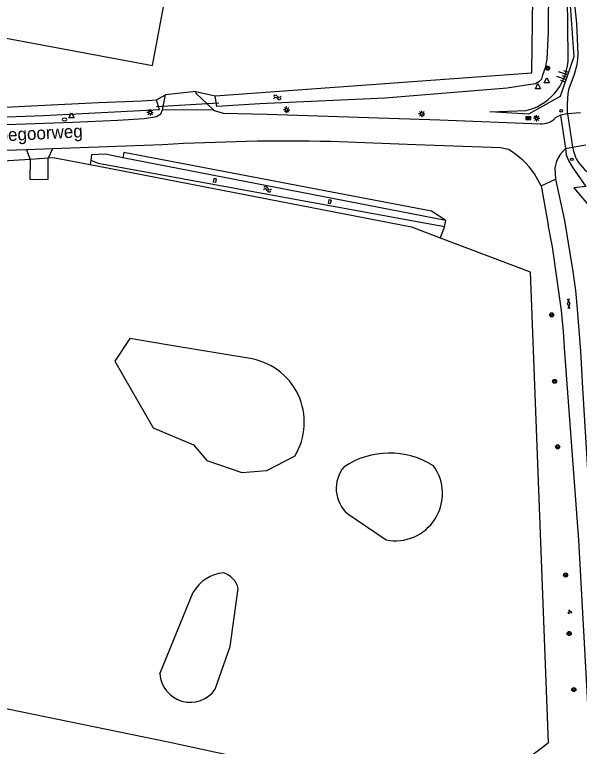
# Model space of a CAD drawing. Extents: x 132994 to 136000, y 393499 to 395512.
# Drawn here: x 133766.6 to 133877.6, y 394251.1 to 394394.8 of the extents above; entities that cross this region are included whole.
import ezdxf

# ---------------------------------------------------------------- set-up
doc = ezdxf.new("R2010")
doc.units = 0
for name, color, linetype in [('gg-afsc-draadraster', 7, 'Continuous'), ('gg-afsc-hekwerk', 7, 'Continuous'), ('gg-anno-openbare ruimte label', 7, 'Continuous'), ('gg-bbg-hoofdgebouw', 7, 'Continuous'), ('gg-knt-BGT kruinlijn', 7, 'Continuous'), ('gg-knt-bovenkant onderkant talud', 7, 'Continuous'), ('gg-knt-bronhoudergrens', 7, 'Continuous'), ('gg-knt-onverhard', 7, 'Continuous'), ('gg-knt-verharding', 7, 'Continuous'), ('gg-kntw-bovenkant insteek waterloop', 7, 'Continuous'), ('gg-kwrk-duiker nz buis', 7, 'Continuous'), ('gt-grn-groengrens', 7, 'Continuous'), ('gt-grn-weggrens', 7, 'Continuous'), ('gt-symb-boom', 7, 'Continuous'), ('gt-symb-brandkraan', 7, 'Continuous'), ('gt-symb-elektrakast', 7, 'Continuous'), ('gt-symb-gesloten verharding', 7, 'Continuous'), ('gt-symb-groenvak', 7, 'Continuous'), ('gt-symb-kolk center center', 7, 'Continuous'), ('gt-symb-lichtmast', 7, 'Continuous'), ('gt-symb-talud symbool', 7, 'Continuous'), ('gt-symb-verkeersbordpaal', 7, 'Continuous'), ('gt-symb-waterafsluiter', 7, 'Continuous'), ('gt-symb-watersymbool', 7, 'Continuous')]:
    doc.layers.add(name, color=color, linetype=linetype)

# ---------------------------------------------------------------- blocks, each defined once
blk = doc.blocks.new('gt0-WAFSL')
at = {"layer": 'gt-symb-waterafsluiter'}
for p, q in [((-0.5, -0.33), (0, 0.67)), ((0, 0.67), (0.5, -0.33)), ((0.5, -0.33), (-0.5, -0.33))]:
    blk.add_line(p, q, dxfattribs=at)
blk = doc.blocks.new('gt0-BOOM')
at = {"layer": 'gt-symb-boom'}
for radius in [0.4, 0.2]:
    blk.add_circle((0, 0), radius, dxfattribs=at)
blk = doc.blocks.new('gt0-TALUD_1')
at = {"layer": 'gt-symb-talud symbool'}
for p, q in [((-1, -1), (-1, 0)), ((-0.5, -2), (-0.5, 0)), ((0, -1), (0, 0)), ((0.5, -2), (0.5, 0)), ((1, -1), (1, 0))]:
    blk.add_line(p, q, dxfattribs=at)
blk = doc.blocks.new('gt0-LMAST')
at = {"layer": 'gt-symb-lichtmast'}
for p, q in [((-0.18, 0.17), (-0.45, 0.44)), ((0, 0.25), (0, 0.62)), ((0.17, 0.17), (0.44, 0.44)), ((-0.25, 0), (-0.63, 0)), ((-0.18, -0.18), (-0.45, -0.45)), ((0, -0.25), (0, -0.63)), ((0.44, -0.45), (0.17, -0.18)), ((0.25, 0), (0.62, 0))]:
    blk.add_line(p, q, dxfattribs=at)
blk.add_circle((0, 0), 0.25, dxfattribs=at)
blk = doc.blocks.new('gt0-VPAAL')
at = {"layer": 'gt-symb-verkeersbordpaal'}
blk.add_circle((0, 0), 0.25, dxfattribs=at)
blk = doc.blocks.new('gt0-GRVAK')
at = {"layer": 'gt-symb-groenvak'}
for p, q in [((-0.11, 0.19), (-0.23, 0.24)), ((-0.18, 0.15), (0.09, 0.15)), ((-0.09, 0.21), (-0.16, 0.32)), ((-0.05, 0.21), (-0.05, 0.39)), ((0, 0.21), (0.06, 0.32)), ((0.01, 0.19), (0.13, 0.24)), ((0.26, -0.05), (0.2, 0.06)), ((0.3, -0.05), (0.3, 0.13)), ((0.35, -0.05), (0.41, 0.06)), ((-0.25, -0.23), (-0.36, -0.18)), ((-0.32, -0.26), (-0.05, -0.26)), ((-0.23, -0.21), (-0.29, -0.1)), ((-0.18, -0.2), (-0.18, -0.02)), ((-0.14, -0.21), (-0.07, -0.1)), ((-0.12, -0.23), (0, -0.18)), ((0.24, -0.07), (0.12, -0.02)), ((0.17, -0.11), (0.44, -0.11)), ((0.37, -0.07), (0.49, -0.02))]:
    blk.add_line(p, q, dxfattribs=at)
blk = doc.blocks.new('gt0-GESVH1')
at = {"layer": 'gt-symb-gesloten verharding'}
for p, q in [((-0.99, -0.26), (0.01, 0.24)), ((0.01, -0.26), (-0.99, 0.24)), ((0.01, 0.24), (1.01, -0.26)), ((1.01, 0.24), (0.01, -0.26))]:
    blk.add_line(p, q, dxfattribs=at)
blk = doc.blocks.new('gt0-WA')
at = {"layer": 'gt-symb-watersymbool'}
for centre, start, end in [((-0.32, 0.02), 28.0725, 151.9275), ((0.43, 0.42), 208.0725, 331.9275), ((-0.32, -0.43), 28.0725, 151.9275), ((0.43, -0.03), 208.0725, 331.9275)]:
    blk.add_arc(centre, 0.425, start, end, dxfattribs=at)
blk = doc.blocks.new('gt0-EKAST')
at = {"layer": 'gt-symb-elektrakast'}
for p, q in [((-0.5, -0.25), (0.5, 0.25)), ((-0.5, 0.25), (0.5, -0.25))]:
    blk.add_line(p, q, dxfattribs=at)
blk.add_lwpolyline([(0.5, 0.25), (-0.5, 0.25), (-0.5, -0.25), (0.5, -0.25)], close=True, dxfattribs=at)
blk = doc.blocks.new('gt0-KOLKCC')
at = {"layer": 'gt-symb-kolk center center'}
blk.add_lwpolyline([(-0.38, 0.2), (0.38, 0.2), (0.38, -0.2), (-0.38, -0.2)], close=True, dxfattribs=at)
blk = doc.blocks.new('gt0-BR')
at = {"layer": 'gt-symb-brandkraan'}
for centre, radius, start, end in [((-0.24, 0), 0.206, 107.5669, 252.4331), ((0.6, -2.66), 3, 106.892, 107.5669), ((0, -0.69), 0.938, 73.108, 106.892), ((-0.6, -2.66), 3, 72.4331, 73.108), ((0.24, 0), 0.206, 287.567, 72.4331), ((0.6, 2.66), 3, 252.4331, 253.108), ((0, 0.69), 0.938, 253.108, 286.8921), ((-0.6, 2.66), 3, 286.8921, 287.567)]:
    blk.add_arc(centre, radius, start, end, dxfattribs=at)

msp = doc.modelspace()

# ---------------------------------------------------------------- linework, layer by layer
at = {"layer": 'gg-afsc-draadraster'}
for p, q in [((133769.7, 394366.38), (133751.16, 394365.24)), ((133773.24, 394366.6), (133769.7, 394366.38)), ((133774.53, 394366.68), (133773.24, 394366.6)), ((133774.53, 394366.68), (133781.44, 394365.34)), ((133850.21, 394350.97), (133867.86, 394344.26)), ((133867.86, 394344.26), (133871.43, 394251.79)), ((133854.87, 394239.41), (133871.43, 394251.79))]:
    msp.add_line(p, q, dxfattribs=at)
for points in [[(133781.44, 394365.34), (133844.57, 394353.11), (133850.21, 394350.97)], [(133837.36, 394243.19), (133796.78, 394251.96), (133765.58, 394258.32), (133761.44, 394259.55), (133756.92, 394262.08), (133753.62, 394264.61), (133733.16, 394282.25), (133750.17, 394360.68)]]:
    msp.add_lwpolyline(points, dxfattribs=at)
at = {"layer": 'gg-afsc-hekwerk'}
for p, q in [((133868.22, 394383.61), (133868.54, 394411.09)), ((133802.23, 394379.67), (133796.25, 394379.02))]:
    msp.add_line(p, q, dxfattribs=at)
at = {"layer": 'gg-bbg-hoofdgebouw'}
msp.add_lwpolyline([(133766.81, 394480.12), (133766.45, 394478.19), (133740.48, 394483.05), (133727.52, 394413.88), (133749.15, 394409.83), (133748.48, 394406.29), (133752.41, 394405.55), (133751.83, 394402.41), (133755.76, 394401.67), (133755.17, 394398.53), (133759.1, 394397.79), (133757.92, 394391.48), (133793.71, 394384.78), (133796.67, 394400.56)], dxfattribs=at)
at = {"layer": 'gg-knt-BGT kruinlijn'}
msp.add_line((133867.54, 394375.27), (133859.98, 394375.72), dxfattribs=at)
msp.add_lwpolyline([(133875.08, 394405.84), (133876.44, 394386.5), (133873.79, 394378.73), (133867.54, 394375.27)], dxfattribs=at)
at = {"layer": 'gg-knt-bovenkant onderkant talud'}
msp.add_line((133875.37, 394386.54), (133875.08, 394405.84), dxfattribs=at)
for points in [[(133859.98, 394375.72), (133867.07, 394375.95), (133867.56, 394376.08)], [(133878.82, 394361.03), (133876.47, 394360.8), (133879.98, 394356.62), (133882.1, 394337.08)]]:
    msp.add_lwpolyline(points, dxfattribs=at)
msp.add_arc((133864.6, 394386.43), 10.76, 285.9485, 0.5611, dxfattribs=at)
at = {"layer": 'gg-knt-bronhoudergrens'}
for p, q in [((133832.07, 394296.76), (133839.6, 394291.63)), ((133795.17, 394265.38), (133801.72, 394281.36))]:
    msp.add_line(p, q, dxfattribs=at)
for points in [[(133769.7, 394366.38), (133769.63, 394362.42), (133773.24, 394362.49), (133773.24, 394366.6)], [(133812.52, 394327.31), (133797.4, 394329.83), (133789.25, 394331.19), (133786.33, 394326.76), (133793.86, 394313.68)], [(133793.86, 394313.68), (133801.74, 394310.3), (133804.37, 394307.25), (133811.28, 394304.89), (133816.16, 394305.26), (133821.63, 394308.11)], [(133806.02, 394262.31), (133808.98, 394270.71), (133810.54, 394282.08)]]:
    msp.add_lwpolyline(points, dxfattribs=at)
for centre, radius, start, end in [((133810.85, 394314.75), 12.67, 328.3536, 82.4308), ((133840.28, 394292.57), 16.13, 57.7202, 123.7151), ((133836.39, 394301.74), 6.6, 140.0239, 229.0469), ((133841.38, 394300.75), 9.29, 258.9782, 35.9696), ((133808.5, 394277.41), 7.85, 96.3396, 149.7333), ((133806.37, 394281.12), 4.28, 13.0451, 72.8363), ((133801.13, 394265.74), 5.98, 183.4236, 324.9548)]:
    msp.add_arc(centre, radius, start, end, dxfattribs=at)
at = {"layer": 'gg-knt-onverhard'}
for p, q in [((133768.98, 394368.26), (133769.7, 394366.38)), ((133774.05, 394368.43), (133773.24, 394366.6))]:
    msp.add_line(p, q, dxfattribs=at)
at = {"layer": 'gg-knt-verharding'}
for p, q in [((133795.7, 394376.07), (133796.25, 394379.02)), ((133795.7, 394376.07), (133805.62, 394376.18)), ((133873.84, 394375.04), (133872.93, 394374.57)), ((133875.22, 394375.3), (133873.84, 394375.04)), ((133873.84, 394375.04), (133874.82, 394368.53)), ((133877.78, 394375.5), (133875.22, 394375.3)), ((133875.22, 394375.3), (133876.23, 394368.74)), ((133795.68, 394369.24), (133774.05, 394368.43)), ((133874.82, 394368.53), (133876.23, 394368.74)), ((133876.23, 394368.74), (133876.38, 394367.96)), ((133774.05, 394368.43), (133768.98, 394368.26)), ((133870.05, 394361.17), (133868.76, 394363.53)), ((133872.88, 394362.5), (133874.63, 394354.4)), ((133870.05, 394361.17), (133871.44, 394353.53))]:
    msp.add_line(p, q, dxfattribs=at)
for points in [[(133875.22, 394375.3), (133875.2, 394377.3), (133875.36, 394379.33), (133875.57, 394380.3), (133876.58, 394383.13), (133877.12, 394385.03), (133877.27, 394386.03), (133877.32, 394387.03), (133877.18, 394390.03), (133877.07, 394393.03), (133875.16, 394411.51)], [(133805.62, 394376.18), (133802.27, 394379.34), (133802.23, 394379.67)], [(133747.37, 394372.58), (133755.61, 394372.9), (133778.06, 394373.68), (133786.87, 394374.04), (133792.1, 394374.4), (133794.51, 394374.79), (133795.36, 394375.33), (133795.7, 394376.07)], [(133805.62, 394376.18), (133805.62, 394376.02), (133807.57, 394375.46), (133816.22, 394375.24), (133850.13, 394374.15), (133869.84, 394373.36)], [(133863.62, 394368.3), (133862.06, 394368.64), (133845.41, 394369.22), (133828.71, 394369.88)], [(133768.98, 394368.26), (133757.12, 394367.85), (133747.61, 394367.57)], [(133874.82, 394368.53), (133873.79, 394367.34), (133873.08, 394366.07), (133872.74, 394364.66), (133872.88, 394362.5)], [(133874.63, 394354.4), (133876.27, 394344.34), (133876.76, 394340.64), (133877.12, 394336.94), (133877.79, 394328.7), (133878.16, 394321.43), (133882.67, 394247.65), (133884.52, 394226.23), (133881.35, 394225.75), (133879.86, 394247.58), (133877.44, 394291.59), (133874.7, 394328.42), (133874.43, 394332.55), (133874.03, 394336.68), (133872.25, 394349.2), (133871.44, 394353.53)]]:
    msp.add_lwpolyline(points, dxfattribs=at)
for centre, radius, start, end in [((133870.2, 394377), 3.65, 264.3384, 318.3735), ((133820.05, 393962.09), 407.87, 88.7838, 93.4258), ((133855.18, 394354.05), 16.56, 34.9061, 59.3686), ((133883.72, 394370.02), 7.62, 195.7254, 232.1614)]:
    msp.add_arc(centre, radius, start, end, dxfattribs=at)
at = {"layer": 'gg-kntw-bovenkant insteek waterloop'}
for p, q in [((133806.36, 394376.75), (133805.99, 394378.87)), ((133795.07, 394376.1), (133794.52, 394378.05)), ((133851.31, 394354.35), (133787.9, 394366.7)), ((133851.05, 394353.2), (133851.31, 394354.35))]:
    msp.add_line(p, q, dxfattribs=at)
for points in [[(133868.54, 394411.09), (133869.66, 394411.2), (133870.7, 394411.19), (133871.26, 394410.81), (133871.54, 394409.88), (133871.41, 394391.43), (133871.13, 394386.02), (133870.85, 394384.33), (133870.31, 394382.92), (133870.09, 394382.12), (133869.57, 394381.61), (133868.94, 394381.19), (133867.58, 394380.99)], [(133805.99, 394378.87), (133868.21, 394383.34), (133868.22, 394383.61)], [(133867.58, 394380.99), (133863.38, 394380.38), (133839.37, 394378.41), (133814.78, 394377.26), (133806.36, 394376.75)], [(133737.89, 394375.65), (133738.79, 394375.62), (133744.84, 394375.66), (133783.11, 394377.51), (133791.65, 394377.84), (133794.52, 394378.05)], [(133795.07, 394376.1), (133772.28, 394374.92), (133761.46, 394374.5), (133744.4, 394373.95), (133739.2, 394373.85), (133738.05, 394373.92)], [(133787.9, 394366.7), (133784.49, 394367.37), (133781.72, 394367.24), (133781.6, 394366.19)], [(133781.6, 394366.19), (133783.01, 394365.62), (133851.05, 394353.2)]]:
    msp.add_lwpolyline(points, dxfattribs=at)
at = {"layer": 'gg-kwrk-duiker nz buis'}
msp.add_line((133794.52, 394376.75), (133806.76, 394377.5), dxfattribs=at)
at = {"layer": 'gt-grn-groengrens'}
for p, q in [((133794.52, 394378.05), (133796.25, 394379.02)), ((133802.23, 394379.67), (133805.99, 394378.87)), ((133781.6, 394366.19), (133781.44, 394365.34)), ((133851.05, 394353.2), (133850.21, 394350.97))]:
    msp.add_line(p, q, dxfattribs=at)
for points in [[(133851.31, 394354.35), (133848.54, 394356.17), (133788.1, 394367.73), (133787.9, 394366.7)], [(133874.82, 394368.53), (133874.97, 394367.29), (133875.51, 394366.02), (133876.25, 394364.69), (133878.82, 394361.03)]]:
    msp.add_lwpolyline(points, dxfattribs=at)
at = {"layer": 'gt-grn-weggrens'}
for p, q in [((133876.23, 394368.74), (133878.81, 394369.24)), ((133870.05, 394361.17), (133872.88, 394362.5))]:
    msp.add_line(p, q, dxfattribs=at)

# ---------------------------------------------------------------- block references
at = {"layer": 'gt-symb-boom'}
for p in [(133871.34, 394384.29), (133872.13, 394335.85), (133872.69, 394322.77), (133873.29, 394309.93), (133874.85, 394284.76), (133875.55, 394273.26), (133876.47, 394262.26)]:
    msp.add_blockref('gt0-BOOM', p, dxfattribs=at)
at = {"layer": 'gt-symb-brandkraan', "rotation": -0.11459140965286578}
msp.add_blockref('gt0-BR', (133776.43, 394374.22), dxfattribs=at)
at = {"layer": 'gt-symb-elektrakast'}
msp.add_blockref('gt0-EKAST', (133867.54, 394374.48), dxfattribs=at)
at = {"layer": 'gt-symb-gesloten verharding', "rotation": 93.61207498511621}
msp.add_blockref('gt0-GESVH1', (133875.45, 394338.02), dxfattribs=at)
at = {"layer": 'gt-symb-groenvak'}
msp.add_blockref('gt0-GRVAK', (133875.66, 394277.51), dxfattribs=at)
at = {"layer": 'gt-symb-kolk center center'}
for p, rotation in [((133805.96, 394362.25), 78.52151796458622), ((133828.53, 394358.06), 76.75619797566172)]:
    msp.add_blockref('gt0-KOLKCC', p, dxfattribs=dict(at, rotation=rotation))
at = {"layer": 'gt-symb-lichtmast'}
for p in [(133793.24, 394375.59), (133820.06, 394376.12), (133846.61, 394375.31), (133869.16, 394374.45)]:
    msp.add_blockref('gt0-LMAST', p, dxfattribs=at)
at = {"layer": 'gt-symb-talud symbool', "xscale": 0.9996224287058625, "yscale": 0.9996224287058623, "rotation": -108.85183578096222}
msp.add_blockref('gt0-TALUD_1', (133875.09, 394382.54), dxfattribs=at)
at = {"layer": 'gt-symb-verkeersbordpaal'}
for p in [(133873.99, 394375.9), (133876.07, 394366.39)]:
    msp.add_blockref('gt0-VPAAL', p, dxfattribs=at)
at = {"layer": 'gt-symb-waterafsluiter'}
for p in [(133871.17, 394381.71), (133869.41, 394380.57), (133777.8, 394374.84)]:
    msp.add_blockref('gt0-WAFSL', p, dxfattribs=at)
at = {"layer": 'gt-symb-watersymbool'}
for p, rotation in [((133818.18, 394378.54), 3.897896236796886), ((133816.34, 394360.47), 168.40926316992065)]:
    msp.add_blockref('gt0-WA', p, dxfattribs=dict(at, rotation=rotation))

# ---------------------------------------------------------------- texts
at = {"layer": 'gg-anno-openbare ruimte label'}
msp.add_text('Stappegoorweg', height=2.5, rotation=3, dxfattribs=at).set_placement((133756.67, 394369.5))

doc.saveas('drawing.dxf')
